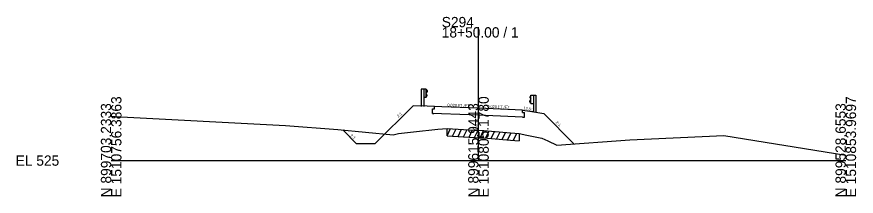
# Model space of a CAD drawing. Extents: x 974 to 2203, y -10 to 19041.
# Drawn here: x 974.3 to 1202.8, y 16990.3 to 17039.1 of the extents above; entities that cross this region are included whole.
import ezdxf

# ---------------------------------------------------------------- set-up
doc = ezdxf.new("R2010")
doc.units = 0
for name, color, linetype in [('RD_GPK_XS_Cell', 7, 'Continuous'), ('RD_XS_Base', 7, 'Continuous'), ('RD_XS_EarthShd', 7, 'Continuous'), ('RD_XS_ExGround', 7, 'Continuous'), ('RD_XS_ExPaveRet', 7, 'Continuous'), ('RD_XS_GR', 7, 'Continuous'), ('RD_XS_Pave', 7, 'Continuous'), ('RD_XS_TX_Elev_EX', 7, 'Continuous'), ('RD_XS_TX_Slope', 7, 'Continuous')]:
    doc.layers.add(name, color=color, linetype=linetype)

msp = doc.modelspace()

# ---------------------------------------------------------------- linework, layer by layer
at = {"layer": 'RD_GPK_XS_Cell'}
for p, q in [((1100, 17000), (1100, 17036.28)), ((1000, 17000), (1100, 17000)), ((1100, 17000), (1200, 17000))]:
    msp.add_line(p, q, dxfattribs=at)
at = {"layer": 'RD_XS_Base'}
for p, q in [((1088, 17014.06), (1088, 17014.7)), ((1087.5, 17012.81), (1087.5, 17014.08)), ((1087.5, 17014.08), (1088, 17014.06)), ((1087.5, 17012.81), (1087.89, 17012.8)), ((1089.89, 17012.72), (1087.89, 17012.8)), ((1099.95, 17012.32), (1089.89, 17012.72)), ((1110, 17011.91), (1099.95, 17012.32)), ((1112, 17013.1), (1112, 17013.74)), ((1112, 17013.1), (1112.5, 17013.08)), ((1112.5, 17011.81), (1112.5, 17013.08)), ((1112, 17011.83), (1110, 17011.91)), ((1112, 17011.83), (1112.5, 17011.81))]:
    msp.add_line(p, q, dxfattribs=at)
at = {"layer": 'RD_XS_EarthShd'}
for p, q in [((1071.82, 17004.55), (1082.2, 17014.93)), ((1086, 17014.78), (1082.2, 17014.93)), ((1088, 17014.7), (1086, 17014.78)), ((1112, 17013.74), (1114, 17013.41)), ((1114, 17013.41), (1117.75, 17012.78)), ((1125.99, 17004.54), (1117.75, 17012.78)), ((1066.82, 17004.55), (1063.04, 17008.33)), ((1071.82, 17004.55), (1066.82, 17004.55))]:
    msp.add_line(p, q, dxfattribs=at)
at = {"layer": 'RD_XS_ExGround'}
msp.add_lwpolyline([(1000, 17012.09), (1000.96, 17011.99), (1047.43, 17009.52), (1061.71, 17008.46), (1076.81, 17007.02), (1078.23, 17007.41), (1082.31, 17007.85), (1088.95, 17008.51), (1091.44, 17008.76), (1098.96, 17008.29), (1100, 17008.23), (1101.42, 17008.16), (1108.74, 17007.53), (1111.05, 17007.35), (1113.15, 17006.93), (1117.26, 17006.12), (1118.88, 17005.39), (1121.34, 17004.19), (1141.18, 17005.67), (1166.84, 17006.83), (1200, 17001.49)], dxfattribs=at)
at = {"layer": 'RD_XS_ExPaveRet'}
for p, q in [((1091.44, 17006.76), (1091.44, 17008.76)), ((1091.44, 17006.76), (1092.41, 17008.7)), ((1092.94, 17006.67), (1093.91, 17008.6)), ((1094.44, 17006.57), (1095.41, 17008.51)), ((1095.94, 17006.48), (1096.91, 17008.41)), ((1097.44, 17006.38), (1098.41, 17008.32)), ((1098.94, 17006.29), (1099.91, 17008.24)), ((1100.44, 17006.21), (1101.41, 17008.16)), ((1101.94, 17006.12), (1102.9, 17008.03)), ((1103.44, 17005.99), (1104.4, 17007.9)), ((1104.94, 17005.86), (1105.9, 17007.78)), ((1106.44, 17005.73), (1107.4, 17007.65)), ((1107.94, 17005.6), (1108.9, 17007.52)), ((1109.44, 17005.48), (1110.4, 17007.4)), ((1091.44, 17006.76), (1098.96, 17006.29)), ((1098.96, 17006.29), (1100, 17006.23)), ((1100, 17006.23), (1101.42, 17006.16)), ((1101.42, 17006.16), (1108.74, 17005.53)), ((1108.74, 17005.53), (1111.05, 17005.35)), ((1111.05, 17007.35), (1111.05, 17005.35))]:
    msp.add_line(p, q, dxfattribs=at)
at = {"layer": 'RD_XS_GR'}
for p, q in [((1084.41, 17019.47), (1084.41, 17014.71)), ((1085.08, 17019.47), (1084.41, 17019.47)), ((1085.08, 17019.47), (1085.08, 17014.68)), ((1085.74, 17019.47), (1085.08, 17019.47)), ((1085.74, 17017.14), (1085.74, 17019.47)), ((1085.74, 17019.33), (1086.01, 17018.93)), ((1086.01, 17018.83), (1085.74, 17018.43)), ((1086.01, 17018.93), (1086.01, 17018.83)), ((1085.74, 17017.14), (1085.08, 17017.14)), ((1086.01, 17017.79), (1085.74, 17018.19)), ((1085.74, 17017.29), (1086.01, 17017.69)), ((1086.01, 17017.69), (1086.01, 17017.79)), ((1114.27, 17017.68), (1114, 17017.28)), ((1114, 17017.28), (1114, 17017.18)), ((1114, 17017.18), (1114.27, 17016.78)), ((1114.27, 17017.82), (1114.94, 17017.82)), ((1114.27, 17015.49), (1114.27, 17017.82)), ((1114.94, 17017.82), (1114.94, 17013.17)), ((1114.94, 17017.82), (1115.6, 17017.82)), ((1115.6, 17017.82), (1115.6, 17013.06)), ((1114, 17016.14), (1114.27, 17016.54)), ((1114, 17016.04), (1114, 17016.14)), ((1114.27, 17015.64), (1114, 17016.04)), ((1114.27, 17015.49), (1114.94, 17015.49))]:
    msp.add_line(p, q, dxfattribs=at)
at = {"layer": 'RD_XS_Pave'}
for p, q in [((1090, 17014.62), (1088, 17014.7)), ((1100, 17014.22), (1090, 17014.62)), ((1110, 17013.82), (1100, 17014.22)), ((1112, 17013.74), (1110, 17013.82))]:
    msp.add_line(p, q, dxfattribs=at)

# ---------------------------------------------------------------- texts
at = {"layer": 'RD_GPK_XS_Cell'}
for s, p in [('S294', (1090, 17036.28)), ('18+50.00 / 1', (1090, 17033.48)), ('EL 525', (974, 16998.6))]:
    msp.add_text(s, height=2.8, dxfattribs=at).set_placement(p)
for s, p in [('E 1510756.3863', (1002.8, 16990)), ('E 1510805.1780', (1102.8, 16990)), ('E 1510853.9697', (1202.8, 16990)), ('N 899703.2333', (1000, 16990)), ('N 899615.9443', (1100, 16990)), ('N 899528.6553', (1200, 16990))]:
    msp.add_text(s, height=2.8, rotation=90, dxfattribs=at).set_placement(p)
at = {"layer": 'RD_XS_TX_Elev_EX'}
msp.add_text('529.12', height=0.75, rotation=90, dxfattribs=at).set_placement((1100, 17008.23))
at = {"layer": 'RD_XS_TX_Slope'}
for s, height, rotation, p in [('0.020 FT./FT.', 0.7518, 357.7673, (1091.53, 17014.75)), ('0.020 FT./FT.', 0.7518, 357.7673, (1102.39, 17014.36)), ('12.5:1', 0.778, 347.2489, (1112.17, 17013.99)), ('2:1', 0.778, 40.6589, (1078.18, 17011.65)), ('2:1', 0.778, 319.3411, (1120.92, 17010.24)), ('2:1', 0.778, 319.3411, (1065.03, 17006.66))]:
    msp.add_text(s, height=height, rotation=rotation, dxfattribs=at).set_placement(p)

doc.saveas('drawing.dxf')
